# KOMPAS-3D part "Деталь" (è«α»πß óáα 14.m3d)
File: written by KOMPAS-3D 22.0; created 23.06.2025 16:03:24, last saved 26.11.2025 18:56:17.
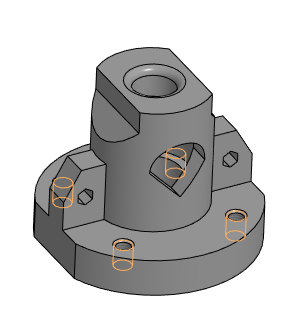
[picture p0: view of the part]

Document properties: Автор: alymovy@yandex.ru; Организация: HP; Полное имя файла: КорпусВариант 14.cdw

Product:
- Body: Тело 3
    Материал: Полиамид П-12Б-20 ТУ 6-05-898-73 (density 1020 kg/m3)
    Масса: 0.583198
- Part/product: Деталь
    Материал: Полиамид П-12Б-20 ТУ 6-05-898-73 (density 1020 kg/m3)
    Масса: 0.580018
    Форматы листов документа: A3

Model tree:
1. Эскиз:1
2. Элемент выдавливания:3
     Расстояние 2 = 25
3. Эскиз:4  (with: Элемент выдавливания:3)
4. Элемент выдавливания:4
     Расстояние 1 = 85
5. Эскиз:5
6. Ребро жесткости:1
     Толщина стенки 1 = 18; Толщина стенки 2 = 1
7. Зеркальный массив:1
8. Экземпляр ( 1 )
9. Экземпляр ( 2 )  (with: Ребро жесткости:1)
10. Эскиз:6  (with: Элемент выдавливания:4, Элемент выдавливания:3)
11. Элемент вращения:1
     Угол 1 = 360
12. Эскиз:7  (with: Элемент выдавливания:4)
13. Элемент выдавливания:5
     Расстояние 1 = 70
14. Эскиз:8  (with: Элемент выдавливания:4)
15. Элемент выдавливания:6
     Расстояние 1 = 70
16. Скругление:1  (with: Элемент вращения:1)
     Радиус = 5
17. Отверстие:1  (with: Элемент выдавливания:3, Ребро жесткости:1)  (labels: M12)
     Глубина выреза = 20; Диаметр отверстия = 10.1056; Угол конуса дна = 118; Расстояние 1 = -29.8909; Расстояние 2 = 103.891; Диаметр зенковки = 13.3056; Глубина зенковки = 1.6; Угол зенковки = 90
18. M12  (labels: cil0_24705-2004 coarse)
     Длина резьбы = 15; Шаг резьбы = 1.75; Номинальный диаметр резьбы = 12
19. Зеркальный массив:2  (with: Экземпляр ( 1 ), Экземпляр ( 2 ), Отверстие:1)
20. Зеркальный массив:3  (with: Экземпляр ( 1 ), Экземпляр ( 2 ), Зеркальный массив:2, Отверстие:1)
21. Экземпляр ( 2 )  (with: Отверстие:1)
22. Эскиз:9  (with: Ребро жесткости:1)
23. Элемент выдавливания:7  (labels: Полиамид П-12Б-20 ТУ 6-05-898-73)
     Расстояние 1 = 61

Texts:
  Линейный размер с обрывом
